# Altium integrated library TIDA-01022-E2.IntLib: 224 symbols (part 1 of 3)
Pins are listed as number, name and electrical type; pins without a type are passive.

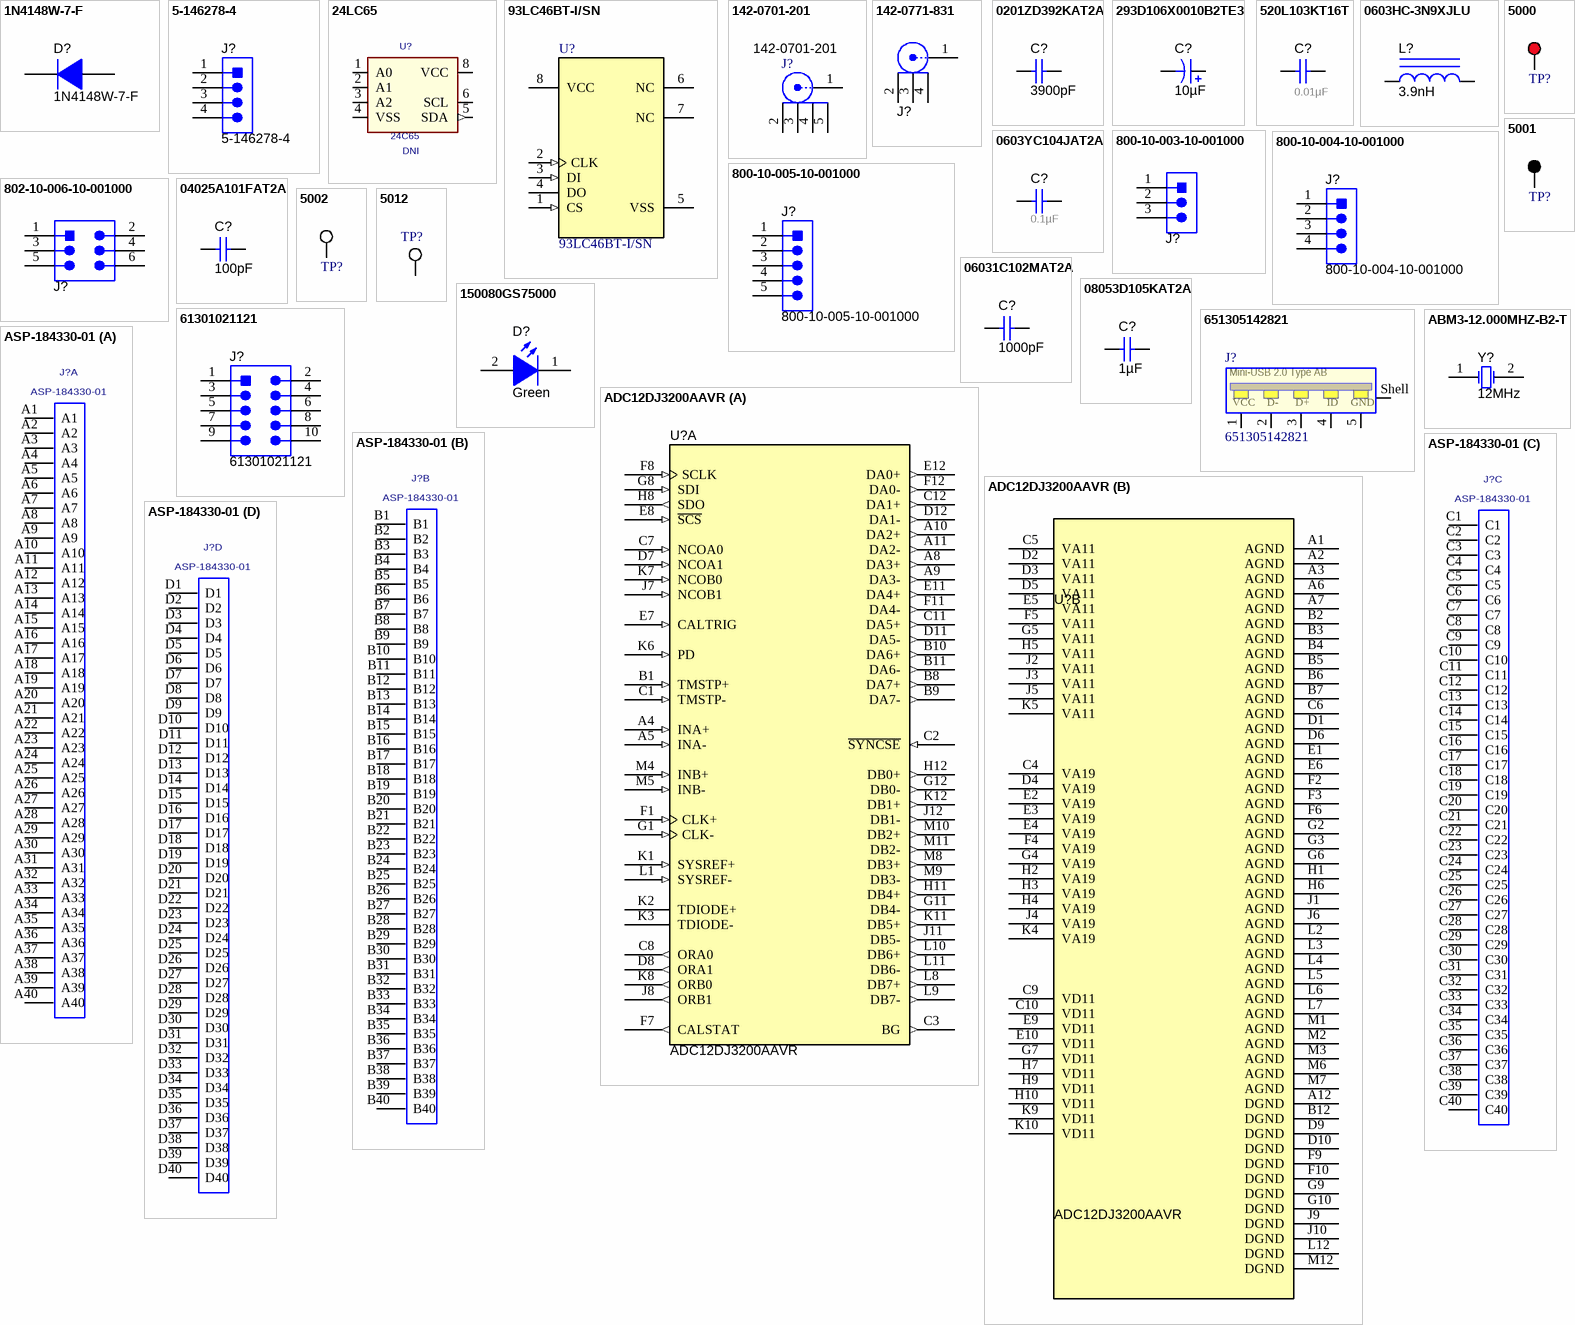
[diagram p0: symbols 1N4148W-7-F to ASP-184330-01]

## 1N4148W-7-F
designator D?
Diode, Ultrafast, 100 V, 0.15 A, SOD-123; Manufacturer: Diodes Inc.; U/M: EA; Vf_V: 1.25; Value: 100V; Value1: 0.15A; Value2: 1.25V; Io_A: 0.15; Vr_V: 100; TJmax_C: 150; SizeAreaWB_mm2: 13.095; SizeArea_mm2: 6.545; SizeX_mm: 3.85; SizeY_mm: 1.7; SizeZ_mm: 1.35; AEC Category: Q101
signal-integrity model Diode
simulation model 1N4148W
footprint SOD-123
pins: 1 K, 2 A

## 5-146278-4
designator J?
Header, 100mil, 4x1, Tin, TH; Manufacturer: TE Connectivity; SymbolCreator: a0412235
footprint TE_5-146278-4
pins: 1, 2, 3, 4

## 24LC65
designator U?, comment 24C65  Note: DNI
64K I2C Smart Serial EEPROM, SOIC-8; PartNumber: 24C65T-I/SM_DNI; Manufacturer: MICROCHIP TECHNOLOGY_DNI; NC: 7
footprint SOIC127P800X216-8N (SOIC, 8-Leads, Body 5.3x5.3mm (max), Pitch 1.27mm, IPC Medium Density)
footprint SO_8_207x207_50
pins: 1 A0, 2 A1, 3 A2, 4 VSS (power), 5 SDA (out), 6 SCL, 8 VCC (power)

## 93LC46BT-I/SN
designator U?
1K Microwire Compatible Serial EEPROM; Manufacturer: Microchip; SymbolCreator: Altium; SizeAreaWB_mm2: 55.131; SizeArea_mm2: 29.351; SizeX_mm: 5.99; SizeY_mm: 4.9; SizeZ_mm: 1.75
footprint SOIC-8
footprint SOIC-8M
footprint SOIC-8L
pins: 1 CS (in), 2 CLK (in), 3 DI (in), 4 DO (hiz), 5 VSS (power), 6 NC, 7 NC, 8 VCC (power)

## 142-0701-201
designator J?
Connector, TH, SMA; Manufacturer: Emerson Network Power; SymbolCreator: X0208326
footprint Johnson_142-0701-20x (Johnson Components recommended land pattern)
pins: 1, 2, 3, 4, 5

## 142-0771-831
designator J?  (value not drawn)
JACK, SMA, 50 Ohm, Gold, Edge Mount; Manufacturer: Johnson; SymbolCreator: Altium; Gender: Female; Voltage_V: 170
footprint Johnson_142-0771-831
pins: 1, 2, 3, 4

## 0201ZD392KAT2A
designator C?  ValueDisplayed: 3900pF  (hidden comment: 0201ZD392KAT2A)
CAP, CERM, 3900 pF, 10 V, +/- 10%, X5R, 0201; Manufacturer: AVX; Polarized: N; CompType: Capacitor; Value: 3900pF; U/M: EA; Cap_F: 0.0000000039; Tolerance_%: 10; Value1: Unknown; Value2: 10V; TaMin_C: -55; TaMax_C: 85; Cap_Case: 0201; SizeArea_mm2: 0.18; SizeAreaWB_mm2: 2.08; SizeX_mm: 0.6; SizeY_mm: 0.3; SizeZ_mm: 0.26; AEC Category: Q200
signal-integrity model Cap
simulation model Cap
footprint 0201
footprint 0201M
footprint 0201L
footprint 0201_Silk
pins: 1, 2

## 293D106X0010B2TE3
designator C?  ValueDisplayed: 10µF  (hidden comment: 293D106X0010B2TE3)
CAP, TA, 10 µF, 10 V, +/- 20%, 2.5 ohm, SMD; Manufacturer: Vishay-Sprague; Polarized: Y; CompType: Capacitor; Value: 10uF; U/M: EA; Cap_F: 0.00001; Tolerance_%: 20; Value1: 2.5 ohm; VDC_V: 10; Value2: 10V; ESR_ohm: 2.5; IRMS_A: 0.18; TaMin_C: -55; TaMax_C: 125; Cap_Case: B; SizeAreaWB_mm2: 17.1; SizeArea_mm2: 9.8; SizeX_mm: 3.5; SizeY_mm: 2.8; SizeZ_mm: 2.1; AEC Category: Q200
signal-integrity model Cap
simulation model Cap
footprint 3528-21
pins: 1 +, 2 -

## 520L103KT16T
designator C?  ValueDisplayed: 0.01µF  (hidden comment: 520L103KT16T)
CAP, CERM, 0.01 µF, 16 V, +/- 10%, X7R, 0402; Manufacturer: AT Ceramics; Polarized: N; CompType: Capacitor; Value: 0.01uF; U/M: EA; Cap_F: 0.00000001; Tolerance_%: 10; Value1: Unknown; VDC_V: 16; Value2: 16V; TaMin_C: -55; TaMax_C: 125; Cap_Case: 0402; AEC Category: Q200; SizeArea_mm2: 0.5; SizeAreaWB_mm2: 3; SizeX_mm: 1; SizeZ_mm: 0.65
signal-integrity model Cap
simulation model Cap
footprint 0402_065
footprint 0402_065M
footprint 0402_065L
footprint 0402_065S
pins: 1, 2

## 0603HC-3N9XJLU
designator L?  ValueDisplayed: 3.9nH  (hidden comment: 0603HC-3N9XJLU)
Inductor, Wirewound, Ceramic, 3.9 nH, 2.2 A, 0.054 ohm, SMD; Manufacturer: Coilcraft; Value: 3.9nH; Ind_H: 3.9E-9; Imax_A: 2.2; Irms: 2.4A @ 20C rise; DCR_ohm: 0.054; Value2: 2.2A; SizeAreaWB_mm2: 5.936; SizeArea_mm2: 2.016; SizeX_mm: 1.8; SizeY_mm: 1.12; SizeZ_mm: 1.02; AEC Category: Q200
signal-integrity model Inductor
simulation model Inductor
footprint 0603HC
pins: 1, 2

## 0603YC104JAT2A
designator C?  ValueDisplayed: 0.1µF  (hidden comment: 0603YC104JAT2A)
CAP, CERM, 0.1uF, 16V, +/-5%, X7R, 0603; Manufacturer: AVX; Cap_Case: 0603; ESR_Ohm: 0.039; Polarized: N; TaMax_C: 125; TaMin_C: -55; Tolerance_%: 5; VDC_V: 16; Cap_F: 0.0000001; CompType: Capacitor; Value1: 0.039 ohm; U/M: EA
signal-integrity model Cap
simulation model Cap
footprint 0603
footprint 0603M
footprint 0603L
footprint 0603_HV
pins: 1, 2

## 800-10-003-10-001000
designator J?  (value not drawn)
Header, 100mil, 3x1, TH; Manufacturer: Mill-Max; SymbolCreator: a0799628
footprint Mill-Max_800-10-003-10-001000
pins: 1, 2, 3
3 alternate drawings of the same symbol

## 800-10-004-10-001000
designator J?
Header, 100mil, 4x1, TH; Manufacturer: Mill-Max; SymbolCreator: a0412235
footprint Mill-Max_800-10-004-10-001000
pins: 1, 2, 3, 4

## 800-10-005-10-001000
designator J?
Header, 100mil, 5x1, TH; Manufacturer: Mill-Max; SymbolCreator: a0412235
footprint Mill-Max_800-10-005-10-001000
pins: 1, 2, 3, 4, 5

## 802-10-006-10-001000
designator J?  (value not drawn)
Header, 2.54 mm, 3x2, Gold, TH; Manufacturer: Mill-Max; SymbolCreator: a0412235; Pitch_mm: 2.54; Gender: Male; Shrouded: N; Row_Count: 2
footprint Mill-Max_802-10-006-10-001000
pins: 1, 2, 3, 4, 5, 6

## 04025A101FAT2A
designator C?  ValueDisplayed: 100pF  (hidden comment: 04025A101FAT2A)
CAP, CERM, 100 pF, 50 V, +/- 1%, C0G/NP0, 0402; Manufacturer: AVX; Polarized: N; CompType: Capacitor; Value: 100pF; U/M: EA; Cap_F: 0.0000000001; Tolerance_%: 1; Value1: Unknown; VDC_V: 50; Value2: 50V; TaMin_C: -55; TaMax_C: 125; Cap_Case: 0402; SizeArea_mm2: 0.5; SizeAreaWB_mm2: 3; SizeZ_mm: 0.6; AEC Category: Q200
signal-integrity model Cap
simulation model Cap
footprint 0402
footprint 0402M
footprint 0402L
footprint 0402S
pins: 1, 2

## 5000
designator TP?  (value not drawn)
Test Point, Miniature, Red, TH; Manufacturer: Keystone; CompType: Test Point Loop; ContactFinish: Silver
footprint Keystone5000
pins: 1

## 5001
designator TP?  (value not drawn)
Test Point, Miniature, Black, TH; Manufacturer: Keystone; CompType: Test Point Loop; ContactFinish: Silver; Green_Lifecycle: Active; Green_REACh: Passed
footprint Keystone5001
pins: 1

## 5002
designator TP?  (value not drawn)
Test Point, Miniature, White, TH; Manufacturer: Keystone; CompType: Test Point Loop; ContactFinish: Silver; Green_Lifecycle: Active; Green_REACh: Passed
footprint Keystone5002
pins: 1

## 5012
designator TP?  (value not drawn)
Test Point, Multipurpose, White, TH; Manufacturer: Keystone; CompType: Test Point Loop; ContactFinish: Silver
footprint Keystone5012
pins: 1

## 06031C102MAT2A
designator C?  ValueDisplayed: 1000pF  (hidden comment: 06031C102MAT2A)
CAP, CERM, 1000 pF, 100 V, +/- 20%, X7R, 0603; Manufacturer: AVX; Polarized: N; CompType: Capacitor; Value: 1000pF; U/M: EA; Cap_F: 0.000000001; Tolerance_%: 20; ESR_ohm: 0.276; Value1: 0.276 ohm; VDC_V: 100; Value2: 100V; TaMin_C: -55; TaMax_C: 125; Cap_Case: 0603; SizeArea_mm2: 1.28; SizeAreaWB_mm2: 4.68; SizeX_mm: 1.6; SizeY_mm: 0.8; SizeZ_mm: 1; AEC Category: Q200
signal-integrity model Cap
simulation model Cap
footprint 0603
footprint 0603M
footprint 0603L
footprint 0603_HV
footprint 0603S
pins: 1, 2

## 08053D105KAT2A
designator C?  ValueDisplayed: 1µF  (hidden comment: 08053D105KAT2A)
CAP, CERM, 1 µF, 25 V, +/- 10%, X5R, 0805; Manufacturer: AVX; Polarized: N; CompType: Capacitor; Value: 1uF; U/M: EA; Cap_F: 0.000001; Tolerance_%: 10; ESR_ohm: 0.012; Value1: 0.012 ohm; VDC_V: 25; Value2: 25V; TaMin_C: -55; TaMax_C: 85; Cap_Case: 0805; SizeArea_mm2: 2.5; SizeAreaWB_mm2: 6.75; SizeX_mm: 2; SizeY_mm: 1.25; SizeZ_mm: 1.45; AEC Category: Q200
signal-integrity model Cap
simulation model Cap
footprint 0805_HV
footprint 0805_HV1
footprint 0805
footprint 0805M
footprint 0805L
pins: 1, 2

## 150080GS75000
designator D?  value Green  (hidden comment: 150080GS75000)
LED, Green, SMD; Manufacturer: Wurth Elektronik; Type: InGaN; Vf_V: 3.2; Value2: 3.2V; Io_A: 0.02; Vr_V: 5; Ir_A: 1e-005; Tjmax_C: 85; Power_TotalModule: 0.105; Value1: 0.105W; Angle: 140; U/M: EA
signal-integrity model Diode
footprint WL-SMCW_Green_0805
pins: 1 K, 2 A

## 61301021121
designator J?
Header, 2.54 mm, 5x2, Gold, TH; Manufacturer: Wurth Elektronik; SymbolCreator: a0412235; Green_Lifecycle: Active; Green_REACh: Passed
footprint WURTH_61301021121
pins: 1, 2, 3, 4, 5, 6, 7, 8, 9, 10

## 651305142821
designator J?
WR-COM Mini USB 2.0 Type AB SMT Horizontal 5 Contacts
footprint 651305142821 (5 pins)
pins: 1 VCC, 2 D-, 3 D+, 4 ID, 5 GND, Shell

## ABM3-12.000MHZ-B2-T
designator Y?  Frequency: 12MHz  (hidden comment: ABM3-12.000MHZ-B2-T)
Crystal, 12Mhz, 18pF, SMD; Manufacturer: Abracon Corporation; SymbolCreator: a0412235; U/M: EA; TaMin_C: -20; TaMax_C: 70; Frequency Stability: ±50ppm
footprint XTAL_ABM3
pins: 1 OSC1, 2 OSC2

## ADC12DJ3200AAVR
designator U?
6.4-GSPS Single Channel or 3.2-GSPS Dual Channel 12-bit Analog-to-Digital Converter (ADC) Family, AAV0144A (FCBGA-144); Alternate PartNumber: ADC12DJ3200AAVT; Manufacturer: Texas Instruments; SymbolCreator: Altium; SizeArea_mm2: 100; SizeAreaWB_mm2: 144; SizeX_mm: 10; SizeZ_mm: 1.94; CompType: IC; U/M: EA
footprint AAV0144A
part A pins: A4 INA+ (in), A5 INA- (in), A8 DA3+ (out), A9 DA3- (out), A10 DA2+ (out), A11 DA2- (out), B1 TMSTP+ (in), B8 DA7+ (out), B9 DA7- (out), B10 DA6+ (out), B11 DA6- (out), C1 TMSTP- (in), C2 ~{SYNCSE} (in), C3 BG (out), C7 NCOA0 (in), C8 ORA0 (out), C11 DA5+ (out), C12 DA1+ (out), D7 NCOA1 (in), D8 ORA1 (out), D11 DA5- (out), D12 DA1- (out), E7 CALTRIG (in), E8 ~{SCS} (in), E11 DA4+ (out), E12 DA0+ (out), F1 CLK+ (in), F7 CALSTAT (out), F8 SCLK (in), F11 DA4- (out), F12 DA0- (out), G1 CLK- (in), G8 SDI (in), G11 DB4- (out), G12 DB0- (out), H8 SDO (out), H11 DB4+ (out), H12 DB0+ (out), J7 NCOB1 (in), J8 ORB1 (out), J11 DB5- (out), J12 DB1- (out), K1 SYSREF+ (in), K2 TDIODE+, K3 TDIODE-, K6 PD (in), K7 NCOB0 (in), K8 ORB0 (out), K11 DB5+ (out), K12 DB1+ (out), L1 SYSREF- (in), L8 DB7+ (out), L9 DB7- (out), L10 DB6+ (out), L11 DB6- (out), M4 INB+ (in), M5 INB- (in), M8 DB3+ (out), M9 DB3- (out), M10 DB2+ (out), M11 DB2- (out)
part B pins: A1 AGND (power), A2 AGND (power), A3 AGND (power), A6 AGND (power), A7 AGND (power), A12 DGND (power), B2 AGND (power), B3 AGND (power), B4 AGND (power), B5 AGND (power), B6 AGND (power), B7 AGND (power), B12 DGND (power), C4 VA19 (power), C5 VA11 (power), C6 AGND (power), C9 VD11 (power), C10 VD11 (power), D1 AGND (power), D2 VA11 (power), D3 VA11 (power), D4 VA19 (power), D5 VA11 (power), D6 AGND (power), D9 DGND (power), D10 DGND (power), E1 AGND (power), E2 VA19 (power), E3 VA19 (power), E4 VA19 (power), E5 VA11 (power), E6 AGND (power), E9 VD11 (power), E10 VD11 (power), F2 AGND (power), F3 AGND (power), F4 VA19 (power), F5 VA11 (power), F6 AGND (power), F9 DGND (power), F10 DGND (power), G2 AGND (power), G3 AGND (power), G4 VA19 (power), G5 VA11 (power), G6 AGND (power), G7 VD11 (power), G9 DGND (power), G10 DGND (power), H1 AGND (power), H2 VA19 (power), H3 VA19 (power), H4 VA19 (power), H5 VA11 (power), H6 AGND (power), H7 VD11 (power), H9 VD11 (power), H10 VD11 (power), J1 AGND (power), J2 VA11 (power), J3 VA11 (power), J4 VA19 (power), J5 VA11 (power), J6 AGND (power), J9 DGND (power), J10 DGND (power), K4 VA19 (power), K5 VA11 (power), K9 VD11 (power), K10 VD11 (power), L2 AGND (power), L3 AGND (power), L4 AGND (power), L5 AGND (power), L6 AGND (power), L7 AGND (power), L12 DGND (power), M1 AGND (power), M2 AGND (power), M3 AGND (power), M6 AGND (power), M7 AGND (power), M12 DGND (power)

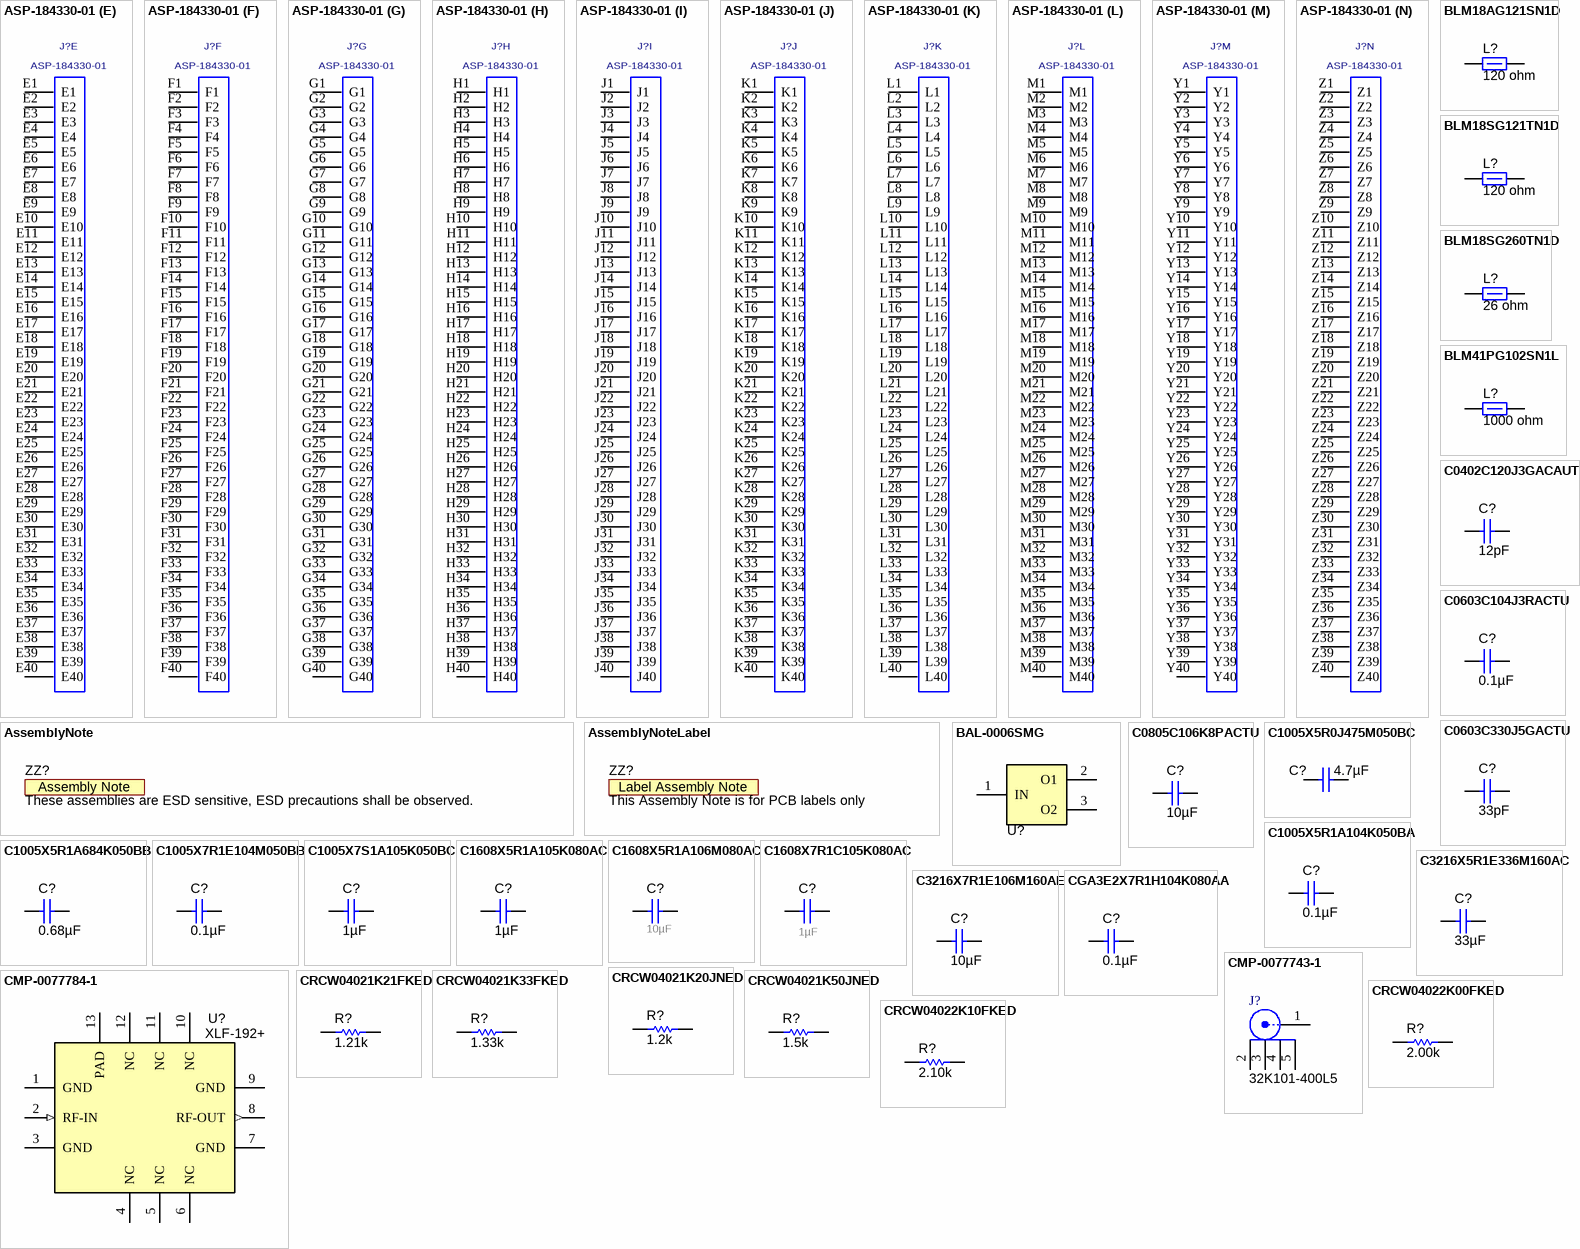
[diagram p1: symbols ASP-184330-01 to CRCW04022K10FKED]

## ASP-184330-01
designator J?
14 ROW .050 PITCH TERMINAL ARRAY ASM.; MANUFACTURER: SAMTEC
footprint ASP-184330-01
part A pins: A1, A2, A3, A4, A5, A6, A7, A8, A9, A10, A11, A12, A13, A14, A15, A16, A17, A18, A19, A20, A21, A22, A23, A24, A25, A26, A27, A28, A29, A30, A31, A32, A33, A34, A35, A36, A37, A38, A39, A40
part B pins: B1, B2, B3, B4, B5, B6, B7, B8, B9, B10, B11, B12, B13, B14, B15, B16, B17, B18, B19, B20, B21, B22, B23, B24, B25, B26, B27, B28, B29, B30, B31, B32, B33, B34, B35, B36, B37, B38, B39, B40
part C pins: C1, C2, C3, C4, C5, C6, C7, C8, C9, C10, C11, C12, C13, C14, C15, C16, C17, C18, C19, C20, C21, C22, C23, C24, C25, C26, C27, C28, C29, C30, C31, C32, C33, C34, C35, C36, C37, C38, C39, C40
part D pins: D1, D2, D3, D4, D5, D6, D7, D8, D9, D10, D11, D12, D13, D14, D15, D16, D17, D18, D19, D20, D21, D22, D23, D24, D25, D26, D27, D28, D29, D30, D31, D32, D33, D34, D35, D36, D37, D38, D39, D40
part E pins: E1, E2, E3, E4, E5, E6, E7, E8, E9, E10, E11, E12, E13, E14, E15, E16, E17, E18, E19, E20, E21, E22, E23, E24, E25, E26, E27, E28, E29, E30, E31, E32, E33, E34, E35, E36, E37, E38, E39, E40
part F pins: F1, F2, F3, F4, F5, F6, F7, F8, F9, F10, F11, F12, F13, F14, F15, F16, F17, F18, F19, F20, F21, F22, F23, F24, F25, F26, F27, F28, F29, F30, F31, F32, F33, F34, F35, F36, F37, F38, F39, F40
part G pins: G1, G2, G3, G4, G5, G6, G7, G8, G9, G10, G11, G12, G13, G14, G15, G16, G17, G18, G19, G20, G21, G22, G23, G24, G25, G26, G27, G28, G29, G30, G31, G32, G33, G34, G35, G36, G37, G38, G39, G40
part H pins: H1, H2, H3, H4, H5, H6, H7, H8, H9, H10, H11, H12, H13, H14, H15, H16, H17, H18, H19, H20, H21, H22, H23, H24, H25, H26, H27, H28, H29, H30, H31, H32, H33, H34, H35, H36, H37, H38, H39, H40
part I pins: J1, J2, J3, J4, J5, J6, J7, J8, J9, J10, J11, J12, J13, J14, J15, J16, J17, J18, J19, J20, J21, J22, J23, J24, J25, J26, J27, J28, J29, J30, J31, J32, J33, J34, J35, J36, J37, J38, J39, J40
part J pins: K1, K2, K3, K4, K5, K6, K7, K8, K9, K10, K11, K12, K13, K14, K15, K16, K17, K18, K19, K20, K21, K22, K23, K24, K25, K26, K27, K28, K29, K30, K31, K32, K33, K34, K35, K36, K37, K38, K39, K40
part K pins: L1, L2, L3, L4, L5, L6, L7, L8, L9, L10, L11, L12, L13, L14, L15, L16, L17, L18, L19, L20, L21, L22, L23, L24, L25, L26, L27, L28, L29, L30, L31, L32, L33, L34, L35, L36, L37, L38, L39, L40
part L pins: M1, M2, M3, M4, M5, M6, M7, M8, M9, M10, M11, M12, M13, M14, M15, M16, M17, M18, M19, M20, M21, M22, M23, M24, M25, M26, M27, M28, M29, M30, M31, M32, M33, M34, M35, M36, M37, M38, M39, M40
part M pins: Y1, Y2, Y3, Y4, Y5, Y6, Y7, Y8, Y9, Y10, Y11, Y12, Y13, Y14, Y15, Y16, Y17, Y18, Y19, Y20, Y21, Y22, Y23, Y24, Y25, Y26, Y27, Y28, Y29, Y30, Y31, Y32, Y33, Y34, Y35, Y36, Y37, Y38, Y39, Y40
part N pins: Z1, Z2, Z3, Z4, Z5, Z6, Z7, Z8, Z9, Z10, Z11, Z12, Z13, Z14, Z15, Z16, Z17, Z18, Z19, Z20, Z21, Z22, Z23, Z24, Z25, Z26, Z27, Z28, Z29, Z30, Z31, Z32, Z33, Z34, Z35, Z36, Z37, Z38, Z39, Z40

## AssemblyNote
designator ZZ?, comment These assemblies are ESD sensitive, ESD precautions shall be observed.  (no BOM)
SymbolCreator: codlsc; CompType: AssemblyNote
footprint AssemblyNote

## AssemblyNoteLabel
designator ZZ?, comment This Assembly Note is for PCB labels only  (no BOM)
SymbolCreator: a0412235
footprint AssemblyNoteLabel

## BAL-0006SMG
designator U?  (value not drawn)
Broadband Balun, 500 kHz to 6 GHz; Manufacturer: Marki Microwave; SymbolCreator: Altium; SizeAreaWB_mm2: 102.6169; SizeArea_mm2: 66.0969; SizeX_mm: 8.13; SizeZ_mm: 3.94
footprint Marki_BAL-0006SMG
pins: 1 IN, 2 O1, 3 O2

## BLM18AG121SN1D
designator L?  ValueDisplayed: 120 ohm  (hidden comment: BLM18AG121SN1D)
Ferrite Bead, 120 ohm @ 100 MHz, 0.5 A, 0603; Manufacturer: MuRata; Value: 120 ohm; Imax_A: 0.5; DCR_ohm: 0.18; Value1: 0.18 ohm; Value2: 0.5A; SizeAreaWB_mm2: 4.68; SizeArea_mm2: 1.28; SizeX_mm: 1.6; SizeY_mm: 0.8; SizeZ_mm: 1; ZTyp@100MHz_Ohm: 120
footprint 0603
footprint 0603M
footprint 0603L
footprint 0603_HV
footprint 0603S
pins: 1, 2

## BLM18SG121TN1D
designator L?  ValueDisplayed: 120 ohm  (hidden comment: BLM18SG121TN1D)
Ferrite Bead, 120 ohm @ 100 MHz, 3 A, 0603; Manufacturer: MuRata; Value: 120 ohm; Imax_A: 3; DCR_ohm: 0.025; Value1: 0.025 ohm; Value2: 3A; SizeAreaWB_mm2: 4.68; SizeArea_mm2: 1.28; SizeX_mm: 1.6; SizeY_mm: 0.8; SizeZ_mm: 1; ZTyp@100MHz_Ohm: 120
footprint 0603
footprint 0603M
footprint 0603L
footprint 0603_HV
footprint 0603S
pins: 1, 2

## BLM18SG260TN1D
designator L?  ValueDisplayed: 26 ohm  (hidden comment: BLM18SG260TN1D)
Ferrite Bead, 26 ohm @ 100 MHz, 6 A, 0603; Manufacturer: MuRata; Value: 26 ohm; Imax_A: 6; DCR_ohm: 0.007; Value1: 0.007 ohm; Value2: 6A; SizeAreaWB_mm2: 4.68; SizeArea_mm2: 1.28; SizeX_mm: 1.6; SizeY_mm: 0.8; SizeZ_mm: 1; ZTyp@100MHz_Ohm: 26
footprint 0603
footprint 0603M
footprint 0603L
footprint 0603_HV
footprint 0603S
pins: 1, 2

## BLM41PG102SN1L
designator L?  ValueDisplayed: 1000 ohm  (hidden comment: BLM41PG102SN1L)
Ferrite Bead, 1000 ohm @ 100 MHz, 1.5 A, 1806; Manufacturer: MuRata; Imax_A: 1.5; DCR_ohm: 0.09; Value1: 0.09 ohm; Value2: 1.5A; SizeAreaWB_mm2: 14.3; SizeArea_mm2: 7.2; SizeX_mm: 4.5; SizeY_mm: 1.6; SizeZ_mm: 1.85; ZTyp@100MHz_Ohm: 1000
footprint 1806_HighSpeed
footprint 1806_HighCurrent
pins: 1, 2

## C0402C120J3GACAUTO
designator C?  ValueDisplayed: 12pF  (hidden comment: C0402C120J3GACAUTO)
CAP, CERM, 12 pF, 25 V, +/- 5%, C0G/NP0, AEC-Q200 Grade 1, 0402; Manufacturer: Kemet; Polarized: N; CompType: Capacitor; Value: 12pF; U/M: EA; Cap_F: 0.000000000012; Tolerance_%: 5; Value1: Unknown; VDC_V: 25; Value2: 25V; TaMin_C: -55; TaMax_C: 125; Cap_Case: 0402; SizeArea_mm2: 0.5; SizeAreaWB_mm2: 3; SizeX_mm: 1; SizeZ_mm: 0.6; AEC Category: Q200; AEC Qualified: Y
signal-integrity model Cap
simulation model Cap
footprint 0402
footprint 0402M
footprint 0402L
footprint 0402S
pins: 1, 2

## C0603C104J3RACTU
designator C?  ValueDisplayed: 0.1µF  (hidden comment: C0603C104J3RACTU)
CAP, CERM, 0.1uF, 25V, +/-5%, X7R, 0603; Manufacturer: Kemet; Cap_Case: 0603; Polarized: N; TaMax_C: 125; TaMin_C: -55; Tolerance_%: 5; VDC_V: 25; Cap_F: 0.0000001; CompType: Capacitor; Value1: Unknown; U/M: EA
signal-integrity model Cap
simulation model Cap
footprint 0603
footprint 0603M
footprint 0603L
footprint 0603_HV
pins: 1, 2

## C0603C330J5GACTU
designator C?  ValueDisplayed: 33pF  (hidden comment: C0603C330J5GACTU)
CAP, CERM, 33pF, 50V, +/-5%, C0G/NP0, 0603; Manufacturer: Kemet; Cap_Case: 0603; Polarized: N; TaMax_C: 125; TaMin_C: -55; Tolerance_%: 5; VDC_V: 50; Cap_F: 0.000000000033; CompType: Capacitor; U/M: EA; Value1: Unknown
signal-integrity model Cap
simulation model Cap
footprint 0603
footprint 0603M
footprint 0603L
footprint 0603_HV
pins: 1, 2

## C0805C106K8PACTU
designator C?  ValueDisplayed: 10µF  (hidden comment: C0805C106K8PACTU)
CAP, CERM, 10uF, 10V, +/-10%, X5R, 0805; Manufacturer: Kemet; Cap_Case: 0805; ESR_Ohm: 0.003; IRMS_A: 11.43; Polarized: N; TaMax_C: 85; TaMin_C: -55; Tolerance_%: 10; Cap_F: 0.00001; CompType: Capacitor; Value1: 0.003 ohm; U/M: EA
signal-integrity model Cap
simulation model Cap
footprint 0805_HV
footprint 0805
footprint 0805M
footprint 0805L
pins: 1, 2

## C1005X5R0J475M050BC
designator C?  ValueDisplayed: 4.7µF  (hidden comment: C1005X5R0J475M050BC)
CAP, CERM, 4.7 µF, 6.3 V, +/- 20%, X5R, 0402; Manufacturer: TDK; Polarized: N; CompType: Capacitor; Value: 4.7uF; U/M: EA; Cap_F: 0.0000047; Tolerance_%: 20; Value1: Unknown; VDC_V: 6.3; Value2: 6.3V; TaMin_C: -55; TaMax_C: 85; Cap_Case: 0402; SizeArea_mm2: 0.5; SizeAreaWB_mm2: 3; SizeX_mm: 1; SizeZ_mm: 0.6; AEC Category: Q200
signal-integrity model Cap
simulation model Cap
footprint 0402
footprint 0402M
footprint 0402L
footprint 0402S
pins: 1, 2

## C1005X5R1A104K050BA
designator C?  ValueDisplayed: 0.1µF  (hidden comment: C1005X5R1A104K050BA)
CAP, CERM, 0.1 µF, 10 V, +/- 10%, X5R, 0402; Manufacturer: TDK; Polarized: N; CompType: Capacitor; Value: 0.1uF; U/M: EA; Cap_F: 0.0000001; Tolerance_%: 10; Value1: Unknown; Value2: 10V; TaMin_C: -55; TaMax_C: 85; Cap_Case: 0402; SizeArea_mm2: 0.5; SizeAreaWB_mm2: 3; SizeX_mm: 1; SizeZ_mm: 0.6; AEC Category: Q200
signal-integrity model Cap
simulation model Cap
footprint 0402
footprint 0402M
footprint 0402L
footprint 0402S
pins: 1, 2

## C1005X5R1A684K050BB
designator C?  ValueDisplayed: 0.68µF  (hidden comment: C1005X5R1A684K050BB)
CAP, CERM, 0.68 µF, 10 V, +/- 10%, X5R, 0402; Manufacturer: TDK; Polarized: N; CompType: Capacitor; Value: 0.68uF; U/M: EA; Cap_F: 0.00000068; Tolerance_%: 10; Value1: Unknown; Value2: 10V; TaMin_C: -55; TaMax_C: 85; Cap_Case: 0402; SizeArea_mm2: 0.5; SizeAreaWB_mm2: 3; SizeX_mm: 1; SizeZ_mm: 0.6; AEC Category: Q200
signal-integrity model Cap
simulation model Cap
footprint 0402
footprint 0402M
footprint 0402L
footprint 0402S
pins: 1, 2

## C1005X7R1E104M050BB
designator C?  ValueDisplayed: 0.1µF  (hidden comment: C1005X7R1E104M050BB)
CAP, CERM, 0.1 µF, 25 V, +/- 20%, X7R, 0402; Manufacturer: TDK; Cap_Case: 0402; Polarized: N; TaMax_C: 125; TaMin_C: -55; Tolerance_%: 20; VDC_V: 25; Cap_F: 0.0000001; CompType: Capacitor; Value: 0.1uF; Value1: Unknown; Value2: 25V; U/M: EA; SizeArea_mm2: 0.5; SizeAreaWB_mm2: 3; SizeX_mm: 1; SizeZ_mm: 0.6; AEC Category: Q200
signal-integrity model Cap
simulation model Cap
footprint 0402
footprint 0402M
footprint 0402L
footprint 0402S
pins: 1, 2

## C1005X7S1A105K050BC
designator C?  ValueDisplayed: 1µF  (hidden comment: C1005X7S1A105K050BC)
CAP, CERM, 1 µF, 10 V, +/- 10%, X7S, 0402; Manufacturer: TDK; Polarized: N; CompType: Capacitor; Value: 1uF; U/M: EA; Cap_F: 0.000001; Tolerance_%: 10; ESR_ohm: 0.011416; Value1: 0.011416 ohm; Value2: 10V; IRMS_A: 1.483; TaMin_C: -55; TaMax_C: 125; Cap_Case: 0402; SizeArea_mm2: 0.5; SizeAreaWB_mm2: 3; SizeX_mm: 1; SizeZ_mm: 0.6; AEC Category: Q200
signal-integrity model Cap
simulation model Cap
footprint 0402
footprint 0402M
footprint 0402L
footprint 0402S
pins: 1, 2

## C1608X5R1A105K080AC
designator C?  ValueDisplayed: 1µF  (hidden comment: C1608X5R1A105K080AC)
CAP, CERM, 1 µF, 10 V, +/- 10%, X5R, 0603; Manufacturer: TDK; Polarized: N; CompType: Capacitor; Value: 1uF; U/M: EA; Cap_F: 0.000001; Tolerance_%: 10; Value1: Unknown; Value2: 10V; TaMin_C: -55; TaMax_C: 85; Cap_Case: 0603; SizeArea_mm2: 1.28; SizeAreaWB_mm2: 4.68; SizeX_mm: 1.6; SizeY_mm: 0.8; SizeZ_mm: 1; AEC Category: Q200
signal-integrity model Cap
simulation model Cap
footprint 0603
footprint 0603M
footprint 0603L
footprint 0603_HV
footprint 0603S
pins: 1, 2

## C1608X5R1A106M080AC
designator C?  ValueDisplayed: 10µF  (hidden comment: C1608X5R1A106M080AC)
CAP, CERM, 10 µF, 10 V, +/- 20%, X5R, 0603; Manufacturer: TDK; Cap_Case: 0603; ESR_ohm: 0.0078; IRMS_A: 1.85; Polarized: N; TaMax_C: 85; TaMin_C: -55; Tolerance_%: 20; VDC_V: 10; Cap_F: 0.00001; CompType: Capacitor; Value: 10uF; U/M: EA; Value1: 0.0078 ohm; Value2: 10V; AEC Category: Q200
signal-integrity model Cap
simulation model Cap
footprint 0603
footprint 0603M
footprint 0603L
footprint 0603_HV
footprint 0603S
pins: 1, 2

## C1608X7R1C105K080AC
designator C?  ValueDisplayed: 1µF  (hidden comment: C1608X7R1C105K080AC)
CAP, CERM, 1 µF, 16 V, +/- 10%, X7R, 0603; Manufacturer: TDK; Cap_Case: 0603; ESR_ohm: 0.0057; Polarized: N; TaMax_C: 125; TaMin_C: -55; Tolerance_%: 10; VDC_V: 16; Cap_F: 0.000001; CompType: Capacitor; Value: 1uF; Value1: 0.0057 ohm; Value2: 16V; U/M: EA; SizeArea_mm2: 1.28; SizeAreaWB_mm2: 4.68; SizeX_mm: 1.6; SizeY_mm: 0.8; SizeZ_mm: 1; AEC Category: Q200
signal-integrity model Cap
simulation model Cap
footprint 0603
footprint 0603M
footprint 0603L
footprint 0603_HV
footprint 0603S
pins: 1, 2

## C3216X5R1E336M160AC
designator C?  ValueDisplayed: 33µF  (hidden comment: C3216X5R1E336M160AC)
CAP, CERM, 33 µF, 25 V, +/- 20%, X5R, 1206; Manufacturer: TDK; Polarized: N; CompType: Capacitor; Value: 33uF; U/M: EA; Cap_F: 0.000033; Tolerance_%: 20; ESR_ohm: 0.002648; Value1: 0.002648 ohm; VDC_V: 25; Value2: 25V; IRMS_A: 4.45864; TaMin_C: -55; TaMax_C: 85; Cap_Case: 1206_180; SizeArea_mm2: 5.12; SizeAreaWB_mm2: 10.92; SizeX_mm: 3.2; SizeY_mm: 1.6; SizeZ_mm: 1.8; AEC Category: Q200
signal-integrity model Cap
simulation model Cap
footprint 1206_180
footprint 1206_180M
footprint 1206_180L
pins: 1, 2

## C3216X7R1E106M160AE
designator C?  ValueDisplayed: 10µF  (hidden comment: C3216X7R1E106M160AE)
CAP, CERM, 10 µF, 25 V, +/- 20%, X7R, 1206_190; Manufacturer: TDK; Polarized: N; CompType: Capacitor; Value: 10uF; U/M: EA; Cap_F: 0.00001; Tolerance_%: 20; Value1: Unknown; VDC_V: 25; Value2: 25V; TaMin_C: -55; TaMax_C: 125; Cap_Case: 1206; SizeArea_mm2: 5.12; SizeAreaWB_mm2: 10.92; SizeX_mm: 3.2; SizeY_mm: 1.6; SizeZ_mm: 1.9; AEC Category: Q200
signal-integrity model Cap
simulation model Cap
footprint 1206_190
footprint 1206_190M
footprint 1206_190L
pins: 1, 2

## CGA3E2X7R1H104K080AA
designator C?  ValueDisplayed: 0.1µF  (hidden comment: CGA3E2X7R1H104K080AA)
CAP, CERM, 0.1 µF, 50 V, +/- 10%, X7R, AEC-Q200 Grade 1, 0603; Manufacturer: TDK; Polarized: N; CompType: Capacitor; Value: 0.1uF; U/M: EA; Cap_F: 0.0000001; Tolerance_%: 10; ESR_ohm: 0.0296; Value1: 0.0296 ohm; VDC_V: 50; Value2: 50V; IRMS_A: 0.97199; TaMin_C: -55; TaMax_C: 125; Cap_Case: 0603; SizeArea_mm2: 1.28; SizeAreaWB_mm2: 4.68; SizeX_mm: 1.6; SizeY_mm: 0.8; SizeZ_mm: 1; AEC Category: Q200; AEC Qualified: Y
signal-integrity model Cap
simulation model Cap
footprint 0603
footprint 0603M
footprint 0603L
footprint 0603_HV
footprint 0603S
pins: 1, 2

## CMP-0077743-1
designator J?, comment 32K101-400L5
SMA, 50 Ohm, Gold, TH; Manufacturer: Rosenberger; Gender: Female; Voltage_V: 480V
footprint Rosenberger_32K101-400L5 (SMA, 50 Ohm, TH)
pins: 1, 2, 3, 4, 5

## CMP-0077784-1
designator U?, comment XLF-192+
Reflectionless Low Pass Filter, SMD; Manufacturer: Minicircuits; SizeArea_mm2: 9; SizeAreaWB_mm2: 16; SizeY_mm: 3; SizeZ_mm: 0.89
footprint DQ1225 (SMD, 12-Leads, Body 3x3mm)
pins: 1 GND (power), 2 RF-IN (in), 3 GND (power), 4 NC, 5 NC, 6 NC, 7 GND (power), 8 RF-OUT (out), 9 GND (power), 10 NC, 11 NC, 12 NC, 13 PAD

## CRCW04021K20JNED
designator R?  ValueDisplayed: 1.2k  (hidden comment: CRCW04021K20JNED)
RES, 1.2 k, 5%, 0.063 W, 0402; Manufacturer: Vishay-Dale; CompType: Resistor; Value: 1.2k; Res_ohm: 1200; Value_Code: 1k20; Tolerance_%: 5; Power_W: 0.063; Value2: 0.063W; VDC_V: 50; TempCo: 200 ppm/C; SizeArea_mm2: 0.5; SizeX_mm: 1; SizeZ_mm: 0.6; EIA_Code: E24; U/M: EA; AEC Category: Q200
signal-integrity model Resistor
simulation model Resistor
footprint 0402
footprint 0402M
footprint 0402L
footprint 0402S
pins: 1, 2

## CRCW04021K21FKED
designator R?  ValueDisplayed: 1.21k  (hidden comment: CRCW04021K21FKED)
RES, 1.21 k, 1%, 0.063 W, 0402; Manufacturer: Vishay-Dale; CompType: Resistor; Value: 1.21k; Res_ohm: 1210; Value_Code: 1k21; Tolerance_%: 1; Power_W: 0.063; Value2: 0.063W; VDC_V: 50; TempCo: 100 ppm/C; SizeArea_mm2: 0.5; SizeZ_mm: 0.6; EIA_Code: E96; U/M: EA; AEC Category: Q200
signal-integrity model Resistor
simulation model Resistor
footprint 0402
footprint 0402M
footprint 0402L
footprint 0402S
pins: 1, 2

## CRCW04021K33FKED
designator R?  ValueDisplayed: 1.33k  (hidden comment: CRCW04021K33FKED)
RES, 1.33 k, 1%, 0.063 W, 0402; Manufacturer: Vishay-Dale; CompType: Resistor; Value: 1.33k; Res_ohm: 1330; Value_Code: 1k33; Tolerance_%: 1; Power_W: 0.063; Value2: 0.063W; VDC_V: 50; TempCo: 100 ppm/C; SizeArea_mm2: 0.5; SizeZ_mm: 0.6; EIA_Code: E96; U/M: EA; AEC Category: Q200
signal-integrity model Resistor
simulation model Resistor
footprint 0402
footprint 0402M
footprint 0402L
footprint 0402S
pins: 1, 2

## CRCW04021K50JNED
designator R?  ValueDisplayed: 1.5k  (hidden comment: CRCW04021K50JNED)
RES, 1.5 k, 5%, 0.063 W, 0402; Manufacturer: Vishay-Dale; CompType: Resistor; Value: 1.5k; Res_ohm: 1500; Value_Code: 1k50; Tolerance_%: 5; Power_W: 0.063; Value2: 0.063W; VDC_V: 50; TempCo: 200 ppm/C; SizeArea_mm2: 0.5; SizeX_mm: 1; SizeZ_mm: 0.6; EIA_Code: E24; U/M: EA; AEC Category: Q200
signal-integrity model Resistor
simulation model Resistor
footprint 0402
footprint 0402M
footprint 0402L
footprint 0402S
pins: 1, 2

## CRCW04022K00FKED
designator R?  ValueDisplayed: 2.00k  (hidden comment: CRCW04022K00FKED)
RES, 2.00 k, 1%, 0.063 W, 0402; Manufacturer: Vishay-Dale; CompType: Resistor; Value: 2.00k; Res_ohm: 2000; Value_Code: 2k00; Tolerance_%: 1; Power_W: 0.063; Value2: 0.063W; VDC_V: 50; TempCo: 100 ppm/C; SizeArea_mm2: 0.5; SizeZ_mm: 0.6; EIA_Code: E96; U/M: EA; AEC Category: Q200
signal-integrity model Resistor
simulation model Resistor
footprint 0402
footprint 0402M
footprint 0402L
footprint 0402S
pins: 1, 2

## CRCW04022K10FKED
designator R?  ValueDisplayed: 2.10k  (hidden comment: CRCW04022K10FKED)
RES, 2.10 k, 1%, 0.063 W, 0402; Manufacturer: Vishay-Dale; CompType: Resistor; Value: 2.10k; Res_ohm: 2100; Value_Code: 2k10; Tolerance_%: 1; Power_W: 0.063; Value2: 0.063W; VDC_V: 50; TempCo: 100 ppm/C; SizeArea_mm2: 0.5; SizeZ_mm: 0.6; EIA_Code: E96; U/M: EA; AEC Category: Q200
signal-integrity model Resistor
simulation model Resistor
footprint 0402
footprint 0402M
footprint 0402L
footprint 0402S
pins: 1, 2

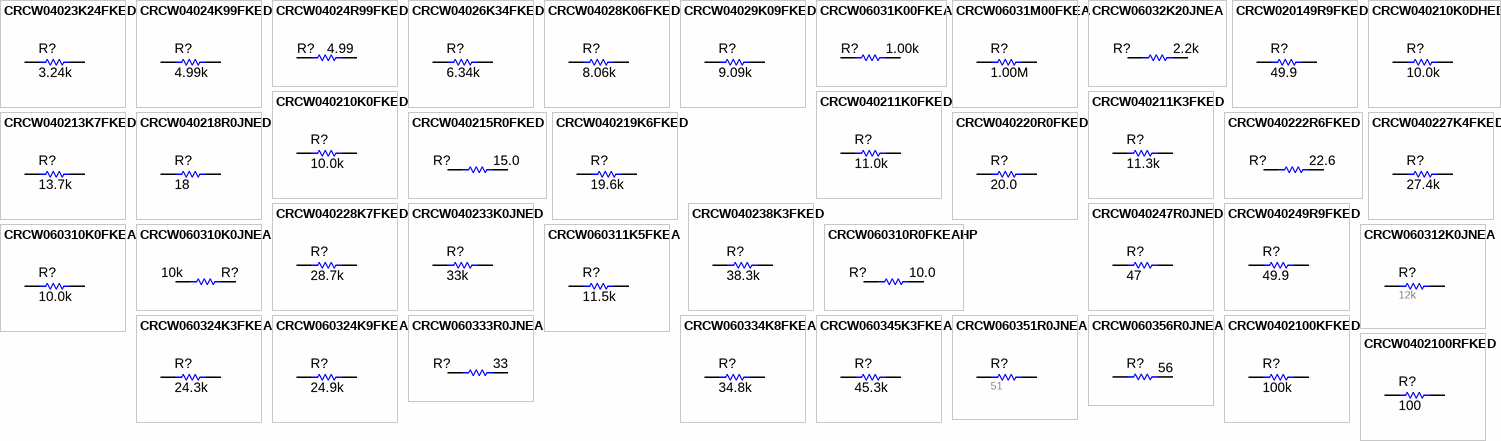
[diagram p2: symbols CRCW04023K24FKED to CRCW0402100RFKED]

## CRCW04023K24FKED
designator R?  ValueDisplayed: 3.24k  (hidden comment: CRCW04023K24FKED)
RES, 3.24 k, 1%, 0.063 W, 0402; Manufacturer: Vishay-Dale; CompType: Resistor; Value: 3.24k; Res_ohm: 3240; Value_Code: 3k24; Tolerance_%: 1; Power_W: 0.063; Value2: 0.063W; VDC_V: 50; TempCo: 100 ppm/C; SizeArea_mm2: 0.5; SizeZ_mm: 0.6; EIA_Code: E96; U/M: EA; AEC Category: Q200
signal-integrity model Resistor
simulation model Resistor
footprint 0402
footprint 0402M
footprint 0402L
footprint 0402S
pins: 1, 2

## CRCW04024K99FKED
designator R?  ValueDisplayed: 4.99k  (hidden comment: CRCW04024K99FKED)
RES, 4.99 k, 1%, 0.063 W, 0402; Manufacturer: Vishay-Dale; CompType: Resistor; Value: 4.99k; Res_ohm: 4990; Value_Code: 4k99; Tolerance_%: 1; Power_W: 0.063; Value2: 0.063W; VDC_V: 50; TempCo: 100 ppm/C; SizeArea_mm2: 0.5; SizeZ_mm: 0.6; EIA_Code: E96; U/M: EA; AEC Category: Q200
signal-integrity model Resistor
simulation model Resistor
footprint 0402
footprint 0402M
footprint 0402L
footprint 0402S
pins: 1, 2

## CRCW04024R99FKED
designator R?  ValueDisplayed: 4.99  (hidden comment: CRCW04024R99FKED)
RES, 4.99, 1%, 0.063 W, 0402; Manufacturer: Vishay-Dale; CompType: Resistor; Value: 4.99; Value_Code: 4R99; Tolerance_%: 1; Power_W: 0.063; Value2: 0.063W; VDC_V: 50; TempCo: 100 ppm/C; SizeArea_mm2: 0.5; SizeZ_mm: 0.6; EIA_Code: E96; U/M: EA; AEC Category: Q200
signal-integrity model Resistor
simulation model Resistor
footprint 0402
footprint 0402M
footprint 0402L
footprint 0402S
pins: 1, 2

## CRCW04026K34FKED
designator R?  ValueDisplayed: 6.34k  (hidden comment: CRCW04026K34FKED)
RES, 6.34 k, 1%, 0.063 W, 0402; Manufacturer: Vishay-Dale; CompType: Resistor; Value: 6.34k; Res_ohm: 6340; Value_Code: 6k34; Tolerance_%: 1; Power_W: 0.063; Value2: 0.063W; VDC_V: 50; TempCo: 100 ppm/C; SizeArea_mm2: 0.5; SizeZ_mm: 0.6; EIA_Code: E96; U/M: EA; AEC Category: Q200
signal-integrity model Resistor
simulation model Resistor
footprint 0402
footprint 0402M
footprint 0402L
footprint 0402S
pins: 1, 2

## CRCW04028K06FKED
designator R?  ValueDisplayed: 8.06k  (hidden comment: CRCW04028K06FKED)
RES, 8.06 k, 1%, 0.063 W, 0402; Manufacturer: Vishay-Dale; CompType: Resistor; Value: 8.06k; Res_ohm: 8060; Value_Code: 8k06; Tolerance_%: 1; Power_W: 0.063; Value2: 0.063W; VDC_V: 50; TempCo: 100 ppm/C; SizeArea_mm2: 0.5; SizeZ_mm: 0.6; EIA_Code: E96; U/M: EA; AEC Category: Q200
signal-integrity model Resistor
simulation model Resistor
footprint 0402
footprint 0402M
footprint 0402L
footprint 0402S
pins: 1, 2

## CRCW04029K09FKED
designator R?  ValueDisplayed: 9.09k  (hidden comment: CRCW04029K09FKED)
RES, 9.09 k, 1%, 0.063 W, 0402; Manufacturer: Vishay-Dale; CompType: Resistor; Value: 9.09k; Res_ohm: 9090; Value_Code: 9k09; Tolerance_%: 1; Power_W: 0.063; Value2: 0.063W; VDC_V: 50; TempCo: 100 ppm/C; SizeArea_mm2: 0.5; SizeZ_mm: 0.6; EIA_Code: E96; U/M: EA; AEC Category: Q200
signal-integrity model Resistor
simulation model Resistor
footprint 0402
footprint 0402M
footprint 0402L
footprint 0402S
pins: 1, 2

## CRCW06031K00FKEA
designator R?  ValueDisplayed: 1.00k  (hidden comment: CRCW06031K00FKEA)
RES, 1.00 k, 1%, 0.1 W, 0603; Manufacturer: Vishay-Dale; CompType: Resistor; Value: 1.00k; Res_ohm: 1000; Value_Code: 1k00; Tolerance_%: 1; Power_W: 0.1; Value2: 0.1W; VDC_V: 75; TempCo: 100 ppm/C; SizeArea_mm2: 1.28; SizeX_mm: 1.6; SizeY_mm: 0.8; EIA_Code: E96; U/M: EA; AEC Category: Q200
signal-integrity model Resistor
simulation model Resistor
footprint 0603
footprint 0603M
footprint 0603L
footprint 0603_HV
footprint 0603S
pins: 1, 2

## CRCW06031M00FKEA
designator R?  ValueDisplayed: 1.00M  (hidden comment: CRCW06031M00FKEA)
RES, 1.00 M, 1%, 0.1 W, 0603; Manufacturer: Vishay-Dale; CompType: Resistor; Value: 1.00Meg; Res_ohm: 1000000; Value_Code: 1M00; Tolerance_%: 1; Power_W: 0.1; Value2: 0.1W; VDC_V: 75; TempCo: 100 ppm/C; SizeArea_mm2: 1.28; SizeX_mm: 1.6; SizeY_mm: 0.8; EIA_Code: E96; U/M: EA; AEC Category: Q200
signal-integrity model Resistor
simulation model Resistor
footprint 0603
footprint 0603M
footprint 0603L
footprint 0603_HV
footprint 0603S
pins: 1, 2

## CRCW06032K20JNEA
designator R?  ValueDisplayed: 2.2k  (hidden comment: CRCW06032K20JNEA)
RES, 2.2 k, 5%, 0.1 W, 0603; Manufacturer: Vishay-Dale; CompType: Resistor; Value: 2.2k; Res_ohm: 2200; Value_Code: 2k20; Tolerance_%: 5; Power_W: 0.1; Value2: 0.1W; VDC_V: 75; TempCo: 200 ppm/C; SizeArea_mm2: 1.28; SizeX_mm: 1.6; SizeY_mm: 0.8; SizeZ_mm: 1; EIA_Code: E24; U/M: EA; AEC Category: Q200
signal-integrity model Resistor
simulation model Resistor
footprint 0603
footprint 0603M
footprint 0603L
footprint 0603_HV
footprint 0603S
pins: 1, 2

## CRCW020149R9FKED
designator R?  ValueDisplayed: 49.9  (hidden comment: CRCW020149R9FKED)
RES, 49.9, 1%, 0.05 W, 0201; Manufacturer: Vishay-Dale; CompType: Resistor; Value: 49.9; Value_Code: 49R9; Tolerance_%: 1; Power_W: 0.05; Value2: 0.05W; VDC_V: 30; TempCo: 100 ppm/C; SizeArea_mm2: 0.18; SizeX_mm: 0.6; SizeY_mm: 0.3; SizeZ_mm: 0.26; EIA_Code: E96; U/M: EA; AEC Category: Q200; AEC Qualified: N
signal-integrity model Resistor
simulation model Resistor
footprint 0201
footprint 0201M
footprint 0201L
footprint 0201_Silk
pins: 1, 2

## CRCW040210K0DHEDP
designator R?  ValueDisplayed: 10.0k  (hidden comment: CRCW040210K0DHEDP)
RES, 10.0 k, 0.5%, 0.063 W, 0402; Manufacturer: Vishay-Dale; CompType: Resistor; Value: 10.0k; Res_ohm: 10000; Value_Code: 10k0; Tolerance_%: 0.5; Power_W: 0.063; Value2: 0.063W; VDC_V: 50; TempCo: 50 ppm/C; SizeX_mm: 1; SizeZ_mm: 0.6; EIA_Code: E192; U/M: EA; AEC Category: Q200
signal-integrity model Resistor
simulation model Resistor
footprint 0402
footprint 0402M
footprint 0402L
footprint 0402S
pins: 1, 2

## CRCW040210K0FKED
designator R?  ValueDisplayed: 10.0k  (hidden comment: CRCW040210K0FKED)
RES, 10.0 k, 1%, 0.063 W, 0402; Manufacturer: Vishay-Dale; CompType: Resistor; Value: 10.0k; Res_ohm: 10000; Value_Code: 10k0; Tolerance_%: 1; Power_W: 0.063; Value2: 0.063W; VDC_V: 50; TempCo: 100 ppm/C; SizeArea_mm2: 0.5; SizeZ_mm: 0.6; EIA_Code: E96; U/M: EA; AEC Category: Q200
signal-integrity model Resistor
simulation model Resistor
footprint 0402
footprint 0402M
footprint 0402L
footprint 0402S
pins: 1, 2

## CRCW040211K0FKED
designator R?  ValueDisplayed: 11.0k  (hidden comment: CRCW040211K0FKED)
RES, 11.0 k, 1%, 0.063 W, 0402; Manufacturer: Vishay-Dale; CompType: Resistor; Value: 11.0k; Res_ohm: 11000; Value_Code: 11k0; Tolerance_%: 1; Power_W: 0.063; Value2: 0.063W; VDC_V: 50; TempCo: 100 ppm/C; SizeArea_mm2: 0.5; SizeZ_mm: 0.6; EIA_Code: E96; U/M: EA; AEC Category: Q200
signal-integrity model Resistor
simulation model Resistor
footprint 0402
footprint 0402M
footprint 0402L
footprint 0402S
pins: 1, 2

## CRCW040211K3FKED
designator R?  ValueDisplayed: 11.3k  (hidden comment: CRCW040211K3FKED)
RES, 11.3 k, 1%, 0.063 W, 0402; Manufacturer: Vishay-Dale; CompType: Resistor; Value: 11.3k; Res_ohm: 11300; Value_Code: 11k3; Tolerance_%: 1; Power_W: 0.063; Value2: 0.063W; VDC_V: 50; TempCo: 100 ppm/C; SizeArea_mm2: 0.5; SizeZ_mm: 0.6; EIA_Code: E96; U/M: EA; AEC Category: Q200
signal-integrity model Resistor
simulation model Resistor
footprint 0402
footprint 0402M
footprint 0402L
footprint 0402S
pins: 1, 2

## CRCW040213K7FKED
designator R?  ValueDisplayed: 13.7k  (hidden comment: CRCW040213K7FKED)
RES, 13.7 k, 1%, 0.063 W, 0402; Manufacturer: Vishay-Dale; CompType: Resistor; Value: 13.7k; Res_ohm: 13700; Value_Code: 13k7; Tolerance_%: 1; Power_W: 0.063; Value2: 0.063W; VDC_V: 50; TempCo: 100 ppm/C; SizeArea_mm2: 0.5; SizeZ_mm: 0.6; EIA_Code: E96; U/M: EA; AEC Category: Q200
signal-integrity model Resistor
simulation model Resistor
footprint 0402
footprint 0402M
footprint 0402L
footprint 0402S
pins: 1, 2

## CRCW040215R0FKED
designator R?  ValueDisplayed: 15.0  (hidden comment: CRCW040215R0FKED)
RES, 15.0, 1%, 0.063 W, 0402; Manufacturer: Vishay-Dale; CompType: Resistor; Value: 15.0; Res_ohm: 15; Value_Code: 15R0; Tolerance_%: 1; Power_W: 0.063; Value2: 0.063W; VDC_V: 50; TempCo: 100 ppm/C; SizeArea_mm2: 0.5; SizeZ_mm: 0.6; EIA_Code: E96; U/M: EA; AEC Category: Q200
signal-integrity model Resistor
simulation model Resistor
footprint 0402
footprint 0402M
footprint 0402L
footprint 0402S
pins: 1, 2

## CRCW040218R0JNED
designator R?  ValueDisplayed: 18  (hidden comment: CRCW040218R0JNED)
RES, 18, 5%, 0.063 W, 0402; Manufacturer: Vishay-Dale; CompType: Resistor; Value: 18; Value_Code: 18R0; Tolerance_%: 5; Power_W: 0.063; Value2: 0.063W; VDC_V: 50; TempCo: 200 ppm/C; EIA_Code: E24; U/M: EA; AEC Category: Q200
signal-integrity model Resistor
simulation model Resistor
footprint 0402
footprint 0402M
footprint 0402L
footprint 0402S
pins: 1, 2

## CRCW040219K6FKED
designator R?  ValueDisplayed: 19.6k  (hidden comment: CRCW040219K6FKED)
RES, 19.6 k, 1%, 0.063 W, 0402; Manufacturer: Vishay-Dale; CompType: Resistor; Value: 19.6k; Res_ohm: 19600; Value_Code: 19k6; Tolerance_%: 1; Power_W: 0.063; Value2: 0.063W; VDC_V: 50; TempCo: 100 ppm/C; SizeArea_mm2: 0.5; SizeZ_mm: 0.6; EIA_Code: E96; U/M: EA; AEC Category: Q200
signal-integrity model Resistor
simulation model Resistor
footprint 0402
footprint 0402M
footprint 0402L
footprint 0402S
pins: 1, 2

## CRCW040220R0FKED
designator R?  ValueDisplayed: 20.0  (hidden comment: CRCW040220R0FKED)
RES, 20.0, 1%, 0.063 W, 0402; Manufacturer: Vishay-Dale; CompType: Resistor; Value: 20.0; Res_ohm: 20; Value_Code: 20R0; Tolerance_%: 1; Power_W: 0.063; Value2: 0.063W; VDC_V: 50; TempCo: 100 ppm/C; SizeArea_mm2: 0.5; SizeZ_mm: 0.6; EIA_Code: E96; U/M: EA; AEC Category: Q200
signal-integrity model Resistor
simulation model Resistor
footprint 0402
footprint 0402M
footprint 0402L
footprint 0402S
pins: 1, 2

## CRCW040222R6FKED
designator R?  ValueDisplayed: 22.6  (hidden comment: CRCW040222R6FKED)
RES, 22.6, 1%, 0.063 W, 0402; Manufacturer: Vishay-Dale; CompType: Resistor; Value: 22.6; Value_Code: 22R6; Tolerance_%: 1; Power_W: 0.063; Value2: 0.063W; VDC_V: 50; TempCo: 100 ppm/C; SizeArea_mm2: 0.5; SizeZ_mm: 0.6; EIA_Code: E96; U/M: EA; AEC Category: Q200
signal-integrity model Resistor
simulation model Resistor
footprint 0402
footprint 0402M
footprint 0402L
footprint 0402S
pins: 1, 2

## CRCW040227K4FKED
designator R?  ValueDisplayed: 27.4k  (hidden comment: CRCW040227K4FKED)
RES, 27.4 k, 1%, 0.063 W, 0402; Manufacturer: Vishay-Dale; CompType: Resistor; Value: 27.4k; Res_ohm: 27400; Value_Code: 27k4; Tolerance_%: 1; Power_W: 0.063; Value2: 0.063W; VDC_V: 50; TempCo: 100 ppm/C; SizeArea_mm2: 0.5; SizeZ_mm: 0.6; EIA_Code: E96; U/M: EA; AEC Category: Q200
signal-integrity model Resistor
simulation model Resistor
footprint 0402
footprint 0402M
footprint 0402L
footprint 0402S
pins: 1, 2

## CRCW040228K7FKED
designator R?  ValueDisplayed: 28.7k  (hidden comment: CRCW040228K7FKED)
RES, 28.7 k, 1%, 0.063 W, 0402; Manufacturer: Vishay-Dale; CompType: Resistor; Value: 28.7k; Res_ohm: 28700; Value_Code: 28k7; Tolerance_%: 1; Power_W: 0.063; Value2: 0.063W; VDC_V: 50; TempCo: 100 ppm/C; SizeArea_mm2: 0.5; SizeZ_mm: 0.6; EIA_Code: E96; U/M: EA; AEC Category: Q200
signal-integrity model Resistor
simulation model Resistor
footprint 0402
footprint 0402M
footprint 0402L
footprint 0402S
pins: 1, 2

## CRCW040233K0JNED
designator R?  ValueDisplayed: 33k  (hidden comment: CRCW040233K0JNED)
RES, 33 k, 5%, 0.063 W, 0402; Manufacturer: Vishay-Dale; CompType: Resistor; Value: 33k; Res_ohm: 33000; Value_Code: 33k0; Tolerance_%: 5; Power_W: 0.063; Value2: 0.063W; VDC_V: 50; TempCo: 200 ppm/C; SizeArea_mm2: 0.5; SizeX_mm: 1; SizeZ_mm: 0.6; EIA_Code: E24; U/M: EA; AEC Category: Q200; Green_Lifecycle: Active; Green_REACh: Passed
signal-integrity model Resistor
simulation model Resistor
footprint 0402
footprint 0402M
footprint 0402L
footprint 0402S
pins: 1, 2

## CRCW040238K3FKED
designator R?  ValueDisplayed: 38.3k  (hidden comment: CRCW040238K3FKED)
RES, 38.3 k, 1%, 0.063 W, 0402; Manufacturer: Vishay-Dale; CompType: Resistor; Value: 38.3k; Res_ohm: 38300; Value_Code: 38k3; Tolerance_%: 1; Power_W: 0.063; Value2: 0.063W; VDC_V: 50; TempCo: 100 ppm/C; SizeArea_mm2: 0.5; SizeZ_mm: 0.6; EIA_Code: E96; U/M: EA; AEC Category: Q200
signal-integrity model Resistor
simulation model Resistor
footprint 0402
footprint 0402M
footprint 0402L
footprint 0402S
pins: 1, 2

## CRCW040247R0JNED
designator R?  ValueDisplayed: 47  (hidden comment: CRCW040247R0JNED)
RES, 47, 5%, 0.063 W, 0402; Manufacturer: Vishay-Dale; CompType: Resistor; Value: 47; Value_Code: 47R0; Tolerance_%: 5; Power_W: 0.063; Value2: 0.063W; VDC_V: 50; TempCo: 200 ppm/C; SizeArea_mm2: 0.5; SizeX_mm: 1; SizeZ_mm: 0.6; EIA_Code: E24; U/M: EA; AEC Category: Q200
signal-integrity model Resistor
simulation model Resistor
footprint 0402
footprint 0402M
footprint 0402L
footprint 0402S
pins: 1, 2

## CRCW040249R9FKED
designator R?  ValueDisplayed: 49.9  (hidden comment: CRCW040249R9FKED)
RES, 49.9, 1%, 0.063 W, 0402; Manufacturer: Vishay-Dale; CompType: Resistor; Value: 49.9; Value_Code: 49R9; Tolerance_%: 1; Power_W: 0.063; Value2: 0.063W; VDC_V: 50; TempCo: 100 ppm/C; EIA_Code: E96; U/M: EA; AEC Category: Q200
signal-integrity model Resistor
simulation model Resistor
footprint 0402
footprint 0402M
footprint 0402L
footprint 0402S
pins: 1, 2

## CRCW060310K0FKEA
designator R?  ValueDisplayed: 10.0k  (hidden comment: CRCW060310K0FKEA)
RES, 10.0 k, 1%, 0.1 W, 0603; Manufacturer: Vishay-Dale; CompType: Resistor; Value: 10.0k; Res_ohm: 10000; Value_Code: 10k0; Tolerance_%: 1; Power_W: 0.1; Value2: 0.1W; VDC_V: 75; TempCo: 100 ppm/C; SizeArea_mm2: 1.28; SizeX_mm: 1.6; SizeY_mm: 0.8; EIA_Code: E96; U/M: EA; AEC Category: Q200
signal-integrity model Resistor
simulation model Resistor
footprint 0603
footprint 0603M
footprint 0603L
footprint 0603_HV
footprint 0603S
pins: 1, 2

## CRCW060310K0JNEA
designator R?  ValueDisplayed: 10k  (hidden comment: CRCW060310K0JNEA)
RES, 10 k, 5%, 0.1 W, 0603; Manufacturer: Vishay-Dale; CompType: Resistor; Value: 10k; Res_ohm: 10000; Value_Code: 10k0; Tolerance_%: 5; Power_W: 0.1; Value2: 0.1W; VDC_V: 75; TempCo: 200 ppm/C; SizeArea_mm2: 1.28; SizeX_mm: 1.6; SizeY_mm: 0.8; SizeZ_mm: 1; EIA_Code: E24; U/M: EA; AEC Category: Q200
signal-integrity model Resistor
simulation model Resistor
footprint 0603
footprint 0603M
footprint 0603L
footprint 0603_HV
footprint 0603S
pins: 1, 2

## CRCW060310R0FKEAHP
designator R?  ValueDisplayed: 10.0  (hidden comment: CRCW060310R0FKEAHP)
RES, 10.0, 1%, 0.25 W, 0603; Manufacturer: Vishay-Dale; CompType: Resistor; Value: 10.0; Res_ohm: 10; Value_Code: 10R0; Tolerance_%: 1; Power_W: 0.25; Value2: 0.25W; VDC_V: 75; TempCo: 100 ppm/C; SizeArea_mm2: 1.28; SizeX_mm: 1.6; SizeY_mm: 0.8; EIA_Code: E96; U/M: EA; AEC Category: Q200
signal-integrity model Resistor
simulation model Resistor
footprint 0603
footprint 0603M
footprint 0603L
footprint 0603_HV
footprint 0603S
pins: 1, 2

## CRCW060311K5FKEA
designator R?  ValueDisplayed: 11.5k  (hidden comment: CRCW060311K5FKEA)
RES, 11.5 k, 1%, 0.1 W, 0603; Manufacturer: Vishay-Dale; CompType: Resistor; Value: 11.5k; Res_ohm: 11500; Value_Code: 11k5; Tolerance_%: 1; Power_W: 0.1; Value2: 0.1W; VDC_V: 75; TempCo: 100 ppm/C; SizeArea_mm2: 1.28; SizeX_mm: 1.6; SizeY_mm: 0.8; EIA_Code: E96; U/M: EA; AEC Category: Q200
signal-integrity model Resistor
simulation model Resistor
footprint 0603
footprint 0603M
footprint 0603L
footprint 0603_HV
footprint 0603S
pins: 1, 2

## CRCW060312K0JNEA
designator R?  value 12k  (hidden comment: CRCW060312K0JNEA)
RES, 12k ohm, 5%, 0.1W, 0603; Manufacturer: Vishay-Dale; CompType: Resistor; Tolerance_%: 5; VDC_V: 75; Power_W: 0.1; Res_ohm: 12000; U/M: EA; Value_Code: 12k0; EIA_Code: E24
signal-integrity model Resistor
simulation model Resistor
footprint 0603
footprint 0603M
footprint 0603L
footprint 0603_HV
pins: 1, 2

## CRCW060324K3FKEA
designator R?  ValueDisplayed: 24.3k  (hidden comment: CRCW060324K3FKEA)
RES, 24.3 k, 1%, 0.1 W, 0603; Manufacturer: Vishay-Dale; CompType: Resistor; Value: 24.3k; Res_ohm: 24300; Value_Code: 24k3; Tolerance_%: 1; Power_W: 0.1; Value2: 0.1W; VDC_V: 75; TempCo: 100 ppm/C; SizeArea_mm2: 1.28; SizeX_mm: 1.6; SizeY_mm: 0.8; EIA_Code: E96; U/M: EA; AEC Category: Q200
signal-integrity model Resistor
simulation model Resistor
footprint 0603
footprint 0603M
footprint 0603L
footprint 0603_HV
footprint 0603S
pins: 1, 2

## CRCW060324K9FKEA
designator R?  ValueDisplayed: 24.9k  (hidden comment: CRCW060324K9FKEA)
RES, 24.9 k, 1%, 0.1 W, 0603; Manufacturer: Vishay-Dale; CompType: Resistor; Value: 24.9k; Res_ohm: 24900; Value_Code: 24k9; Tolerance_%: 1; Power_W: 0.1; Value2: 0.1W; VDC_V: 75; TempCo: 100 ppm/C; SizeArea_mm2: 1.28; SizeX_mm: 1.6; SizeY_mm: 0.8; EIA_Code: E96; U/M: EA; AEC Category: Q200
signal-integrity model Resistor
simulation model Resistor
footprint 0603
footprint 0603M
footprint 0603L
footprint 0603_HV
footprint 0603S
pins: 1, 2

## CRCW060333R0JNEA
designator R?  ValueDisplayed: 33  (hidden comment: CRCW060333R0JNEA)
RES, 33, 5%, 0.1 W, 0603; Manufacturer: Vishay-Dale; CompType: Resistor; Value: 33; Value_Code: 33R0; Tolerance_%: 5; Power_W: 0.1; Value2: 0.1W; VDC_V: 75; TempCo: 200 ppm/C; SizeArea_mm2: 1.28; SizeX_mm: 1.6; SizeY_mm: 0.8; SizeZ_mm: 1; EIA_Code: E24; U/M: EA; AEC Category: Q200
signal-integrity model Resistor
simulation model Resistor
footprint 0603
footprint 0603M
footprint 0603L
footprint 0603_HV
footprint 0603S
pins: 1, 2

## CRCW060334K8FKEA
designator R?  ValueDisplayed: 34.8k  (hidden comment: CRCW060334K8FKEA)
RES, 34.8 k, 1%, 0.1 W, 0603; Manufacturer: Vishay-Dale; CompType: Resistor; Value: 34.8k; Res_ohm: 34800; Value_Code: 34k8; Tolerance_%: 1; Power_W: 0.1; Value2: 0.1W; VDC_V: 75; TempCo: 100 ppm/C; SizeArea_mm2: 1.28; SizeX_mm: 1.6; SizeY_mm: 0.8; EIA_Code: E96; U/M: EA; AEC Category: Q200
signal-integrity model Resistor
simulation model Resistor
footprint 0603
footprint 0603M
footprint 0603L
footprint 0603_HV
footprint 0603S
pins: 1, 2

## CRCW060345K3FKEA
designator R?  ValueDisplayed: 45.3k  (hidden comment: CRCW060345K3FKEA)
RES, 45.3 k, 1%, 0.1 W, 0603; Manufacturer: Vishay-Dale; CompType: Resistor; Value: 45.3k; Res_ohm: 45300; Value_Code: 45k3; Tolerance_%: 1; Power_W: 0.1; Value2: 0.1W; VDC_V: 75; TempCo: 100 ppm/C; SizeArea_mm2: 1.28; SizeX_mm: 1.6; SizeY_mm: 0.8; EIA_Code: E96; U/M: EA; AEC Category: Q200
signal-integrity model Resistor
simulation model Resistor
footprint 0603
footprint 0603M
footprint 0603L
footprint 0603_HV
footprint 0603S
pins: 1, 2

## CRCW060351R0JNEA
designator R?  ValueDisplayed: 51  (hidden comment: CRCW060351R0JNEA)
RES, 51, 5%, 0.1 W, 0603; Manufacturer: Vishay-Dale; CompType: Resistor; Value: 51; Value_Code: 51R0; Tolerance_%: 5; Power_W: 0.1; Value2: 0.1W; VDC_V: 75; TempCo: 200 ppm/C; EIA_Code: E24; U/M: EA; SizeArea_mm2: 1.28; SizeX_mm: 1.6; SizeY_mm: 0.8; SizeZ_mm: 1; AEC Category: Q200
signal-integrity model Resistor
simulation model Resistor
footprint 0603
footprint 0603M
footprint 0603L
footprint 0603_HV
footprint 0603S
pins: 1, 2

## CRCW060356R0JNEA
designator R?  ValueDisplayed: 56  (hidden comment: CRCW060356R0JNEA)
RES, 56, 5%, 0.1 W, 0603; Manufacturer: Vishay-Dale; CompType: Resistor; Tolerance_%: 5; VDC_V: 75; Power_W: 0.1; Value: 56; U/M: EA; Value_Code: 56R0; Value2: 0.1W; EIA_Code: E24; TempCo: 200 ppm/C; SizeArea_mm2: 1.28; SizeX_mm: 1.6; SizeY_mm: 0.8; SizeZ_mm: 1; AEC Category: Q200
signal-integrity model Resistor
simulation model Resistor
footprint 0603
footprint 0603M
footprint 0603L
footprint 0603_HV
footprint 0603S
pins: 1, 2

## CRCW0402100KFKED
designator R?  ValueDisplayed: 100k  (hidden comment: CRCW0402100KFKED)
RES, 100 k, 1%, 0.063 W, 0402; Manufacturer: Vishay-Dale; CompType: Resistor; Value: 100k; Res_ohm: 100000; Tolerance_%: 1; Power_W: 0.063; Value2: 0.063W; VDC_V: 50; TempCo: 100 ppm/C; SizeArea_mm2: 0.5; SizeZ_mm: 0.6; EIA_Code: E96; U/M: EA; AEC Category: Q200; Green_Lifecycle: Active; Green_REACh: Passed
signal-integrity model Resistor
simulation model Resistor
footprint 0402
footprint 0402M
footprint 0402L
footprint 0402S
pins: 1, 2

## CRCW0402100RFKED
designator R?  ValueDisplayed: 100  (hidden comment: CRCW0402100RFKED)
RES, 100, 1%, 0.063 W, 0402; Manufacturer: Vishay-Dale; CompType: Resistor; Value: 100; Value_Code: 100R; Tolerance_%: 1; Power_W: 0.063; Value2: 0.063W; VDC_V: 50; TempCo: 100 ppm/C; SizeArea_mm2: 0.5; SizeZ_mm: 0.6; EIA_Code: E96; U/M: EA; AEC Category: Q200
signal-integrity model Resistor
simulation model Resistor
footprint 0402
footprint 0402M
footprint 0402L
footprint 0402S
pins: 1, 2

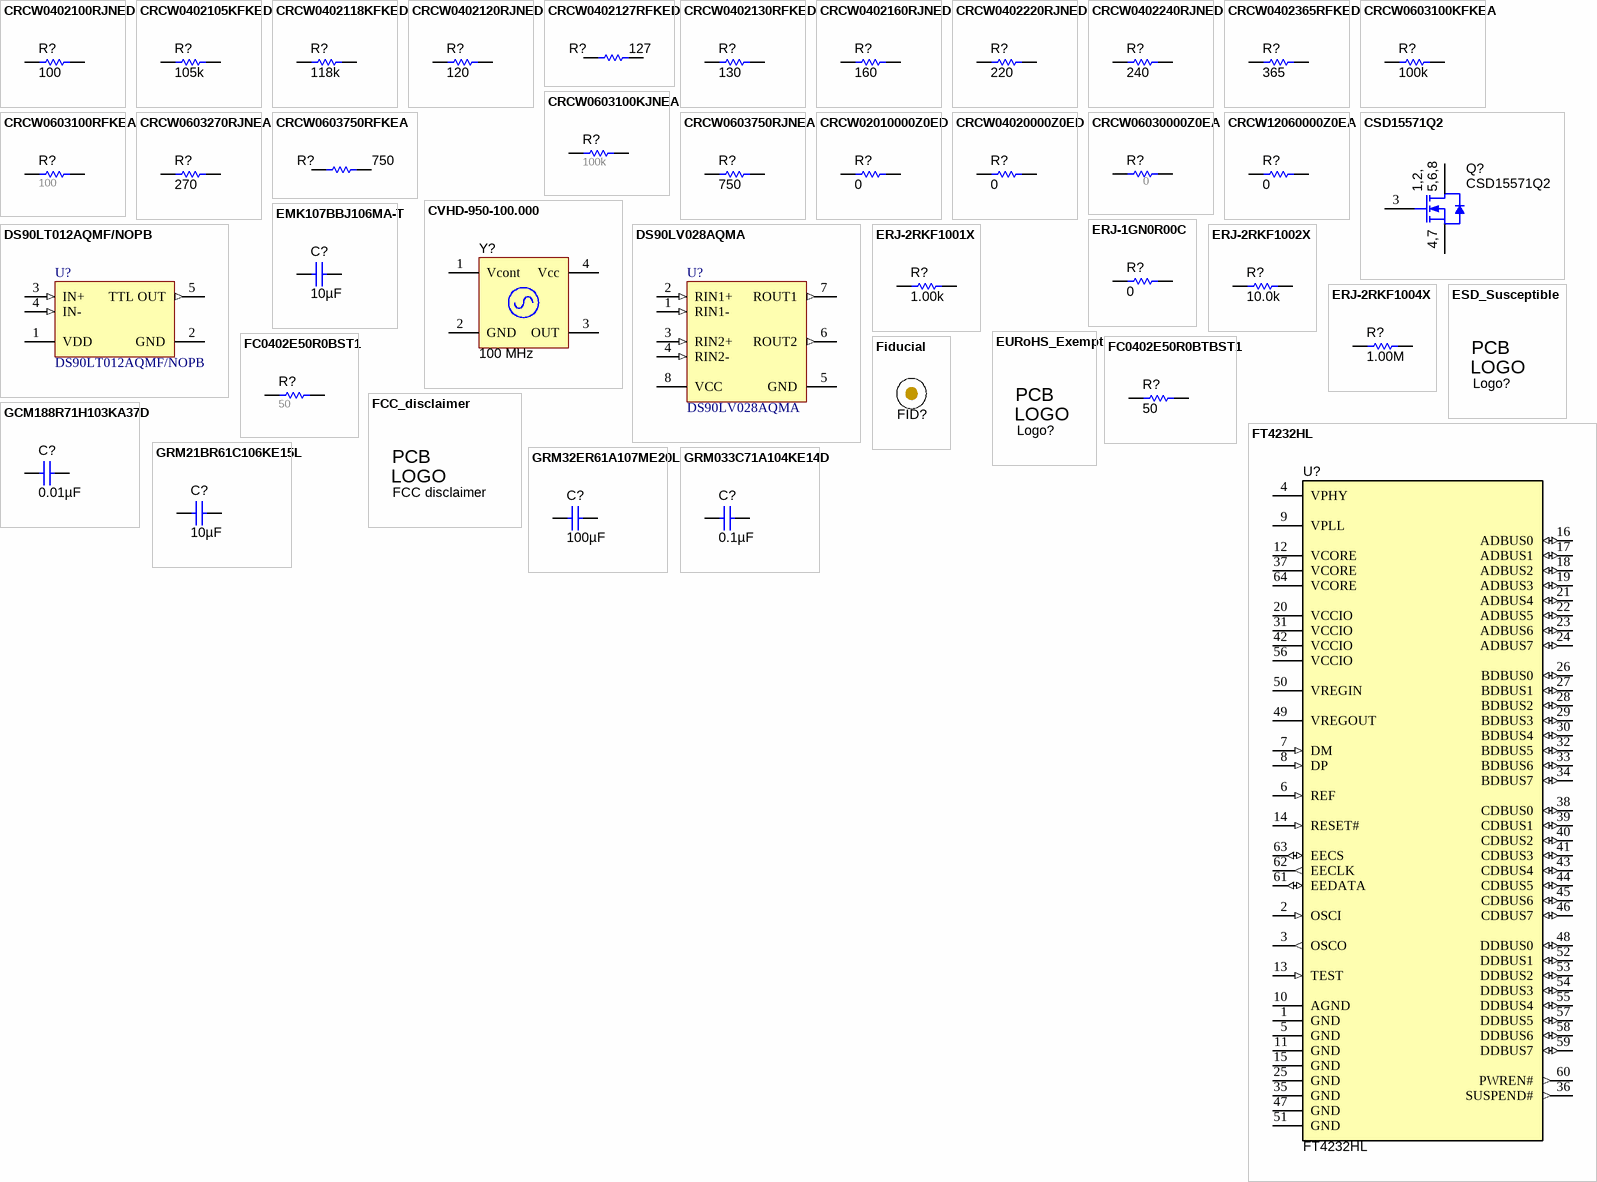
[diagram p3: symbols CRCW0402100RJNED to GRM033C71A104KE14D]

## CRCW0402100RJNED
designator R?  ValueDisplayed: 100  (hidden comment: CRCW0402100RJNED)
RES, 100, 5%, 0.063 W, 0402; Manufacturer: Vishay-Dale; CompType: Resistor; Value: 100; Value_Code: 100R; Tolerance_%: 5; Power_W: 0.063; Value2: 0.063W; VDC_V: 50; TempCo: 200 ppm/C; SizeArea_mm2: 0.5; SizeX_mm: 1; SizeZ_mm: 0.6; EIA_Code: E24; U/M: EA; AEC Category: Q200
signal-integrity model Resistor
simulation model Resistor
footprint 0402
footprint 0402M
footprint 0402L
footprint 0402S
pins: 1, 2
